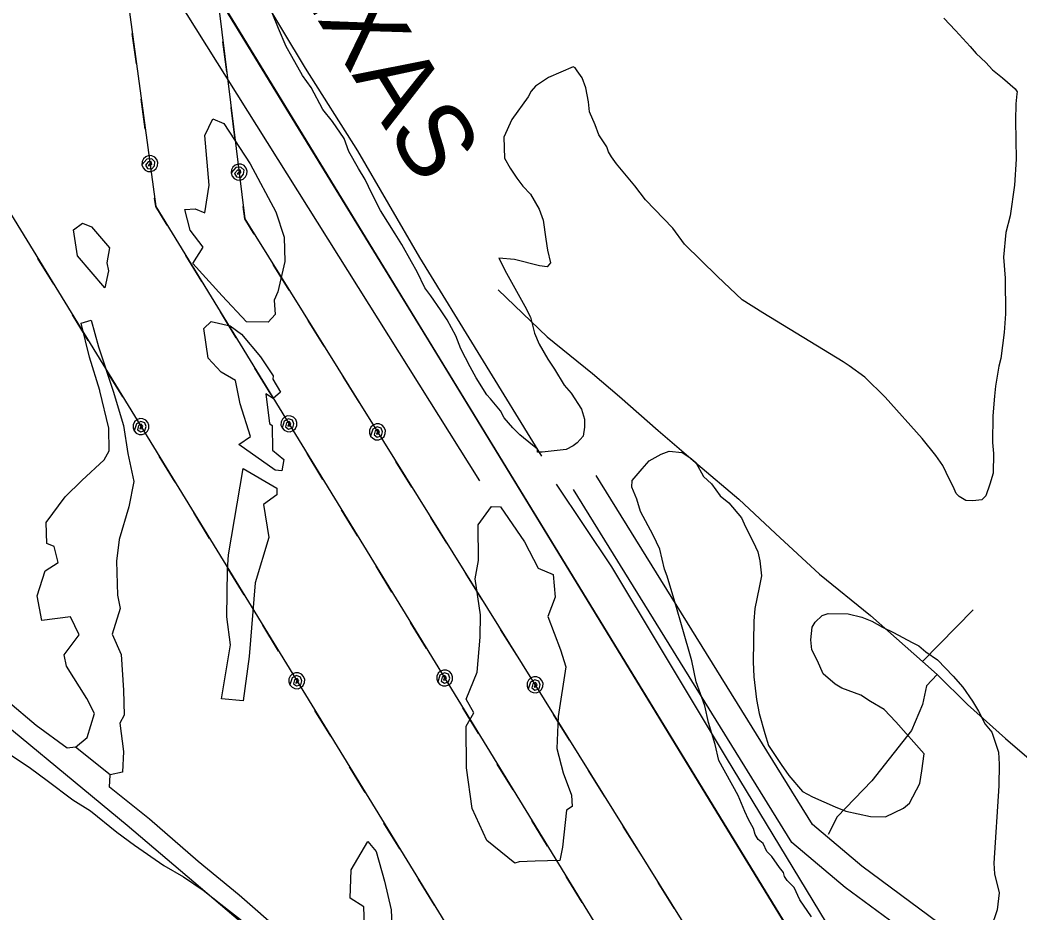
# Model space of a CAD drawing. Extents: x 3263578 to 3301413, y 764927 to 798602.
# Drawn here: x 3268720 to 3269840, y 779917 to 780917 of the extents above; entities that cross this region are included whole.
import ezdxf

# ---------------------------------------------------------------- set-up
doc = ezdxf.new("R2010")
doc.units = 0
for name, color, linetype in [('V-RAIL-IDEN', 7, 'Continuous'), ('V-RAIL-TRAK', 7, 'Continuous'), ('V-ROAD-CNTR', 7, 'Continuous'), ('V-SITE-VEGE', 7, 'Continuous'), ('V-TOPO-SHOR', 7, 'Continuous'), ('V-UTIL-LINE', 7, 'Continuous')]:
    doc.layers.add(name, color=color, linetype=linetype)

msp = doc.modelspace()

# ---------------------------------------------------------------- linework, layer by layer
at = {"layer": 'V-RAIL-TRAK'}
msp.add_lwpolyline([(3270536.8, 778335.8), (3270418.2, 778530.3), (3270314.9, 778698.6), (3270283.6, 778749.8), (3270207, 778874.9), (3270093.6, 779060.7), (3269973.2, 779257.5), (3269816.8, 779512.8), (3269677.5, 779741), (3269504.9, 780022.9), (3269364.8, 780252.1), (3269178.7, 780556.8), (3269021.9, 780812.1), (3268822.8, 781137.8), (3268625.6, 781460.3)], dxfattribs=at)
at = {"layer": 'V-ROAD-CNTR'}
for points in [[(3272188.4, 775832.5), (3271868.1, 776292.7), (3271339.6, 777053.2), (3271160.7, 777323.7), (3270905.4, 777727.5), (3270283.4, 778748.1), (3269657.5, 779774.1), (3268620.7, 781469), (3267728.6, 782934.3)], [(3270148, 779651.3), (3270027.1, 779737), (3269970.2, 779772.8), (3269878.4, 779823.7), (3269781.7, 779881.3), (3269663.2, 779969), (3269607.8, 780015.7), (3269365.5, 780407)], [(3270130.7, 779626.8), (3270010.4, 779712.1), (3269955, 779747), (3269863.4, 779797.7), (3269765.1, 779856.3), (3269644.6, 779945.4), (3269584.8, 779995.8), (3269340, 780391.2)], [(3269089, 779803.1), (3268839.7, 780014.8), (3268651.7, 780170)]]:
    msp.add_lwpolyline(points, dxfattribs=at)
at = {"layer": 'V-SITE-VEGE'}
for p, q in [((3268699.8, 780100.4), (3268731.6, 780078.8)), ((3268731.6, 780078.8), (3268750.3, 780065.2)), ((3268750.3, 780065.2), (3268778.9, 780043.6)), ((3268778.9, 780043.6), (3268798.7, 780031.1)), ((3268798.7, 780031.1), (3268828.3, 780007.3)), ((3268828.3, 780007.3), (3268848, 779992.5)), ((3268848, 779992.5), (3268881, 779969.8)), ((3268881, 779969.8), (3268903, 779957.2)), ((3268903, 779957.2), (3268925, 779942.4)), ((3268925, 779942.4), (3268944.8, 779926.5)), ((3268944.8, 779926.5), (3268975.5, 779902.7))]:
    msp.add_line(p, q, dxfattribs=at)
for points in [[(3269123.9, 780703.7), (3269114.2, 780722.7), (3269106.7, 780738.4), (3269099.1, 780750.7), (3269088.3, 780769.8), (3269083, 780784.3), (3269070, 780803.4), (3269059.1, 780816.9), (3269046.1, 780841.6), (3269036.3, 780855.1), (3269024.5, 780876.4), (3269018, 780887.6), (3269009.4, 780907.7), (3268996.6, 780939)], [(3269755.2, 780919.1), (3269768.3, 780905.5), (3269784.7, 780887.5), (3269791.2, 780879.6), (3269802.2, 780869.4), (3269809.8, 780861.5), (3269820.8, 780852.5), (3269835, 780840), (3269837.2, 780836.7), (3269837.1, 780834.4), (3269835.9, 780823.3), (3269835.6, 780804.5), (3269836, 780761.1), (3269834.4, 780732.3), (3269829.4, 780697.9), (3269824.6, 780679.1), (3269822, 780651.3)], [(3269811.7, 780495.9), (3269810.2, 780473.7), (3269809.8, 780443.8), (3269810.7, 780431.5), (3269810.3, 780409.3), (3269806.8, 780397.1), (3269802.1, 780383.9), (3269797.6, 780379.5), (3269787.6, 780378.5), (3269779.8, 780378.7), (3269772.1, 780383.2), (3269768.8, 780386.6), (3269765.6, 780394.5), (3269761.3, 780402.3), (3269753.8, 780418), (3269746.2, 780429.2), (3269730.9, 780448.3), (3269689.5, 780494.6), (3269666.5, 780517.2), (3269648.9, 780529.7), (3269642.3, 780534.2), (3269552.1, 780589), (3269529, 780603.8), (3269501.6, 780629.8), (3269464.4, 780666), (3269451.4, 780684), (3269420.8, 780715.6), (3269408.8, 780731.3), (3269388.1, 780756.1), (3269382.7, 780764), (3269379.4, 780769.6), (3269377.3, 780775.1), (3269368.6, 780788.6), (3269364.4, 780799.8), (3269357.9, 780814.4), (3269357, 780825.5), (3269353.9, 780841.1), (3269349.6, 780852.3), (3269344.2, 780860.1), (3269342, 780863.5), (3269339.8, 780864.6), (3269311.9, 780852.9), (3269297.3, 780843.1), (3269292.7, 780837.6), (3269289.3, 780831), (3269271.1, 780805.7), (3269261.9, 780785.9), (3269262.6, 780762.5), (3269269.1, 780751.3), (3269276.7, 780740.1), (3269283.2, 780731.1), (3269292, 780722.1), (3269301.7, 780705.2), (3269306, 780693), (3269309, 780671.8), (3269311, 780659.5), (3269314.1, 780645.1), (3269310.7, 780640.7), (3269301.8, 780641.9), (3269274.1, 780649), (3269256.4, 780650.4), (3269265, 780633.6), (3269285.5, 780596.6), (3269292, 780584.3), (3269296.2, 780566.4), (3269301.5, 780554.1), (3269311.2, 780537.3), (3269318.8, 780526.1), (3269329.7, 780508.1), (3269337.3, 780499.1), (3269349.2, 780481.1), (3269352.4, 780470), (3269352.2, 780461.1), (3269351, 780451.1), (3269344.2, 780443.4), (3269339.7, 780440.2), (3269331.8, 780435.9), (3269321.8, 780434.9), (3269305.1, 780433), (3269299.6, 780433.1), (3269299.6, 780436.4), (3269294.1, 780440.9), (3269279.9, 780452.3), (3269272.2, 780460.2), (3269262.4, 780471.4), (3269258.1, 780479.3), (3269247.2, 780492.8), (3269242.8, 780497.3), (3269230.9, 780516.4), (3269224.4, 780528.7), (3269213.6, 780548.9), (3269208.3, 780563.4), (3269198.6, 780581.3), (3269191, 780592.6), (3269180.2, 780608.3), (3269173.6, 780617.3), (3269165, 780635.2), (3269158.5, 780646.4), (3269147.7, 780665.5), (3269140.2, 780677.8), (3269123.9, 780703.7)], [(3269822, 780651.3), (3269823.8, 780628), (3269824.3, 780588), (3269822.9, 780566.9), (3269819.1, 780538), (3269816.7, 780529.2), (3269813, 780507), (3269811.7, 780495.9)], [(3269606.8, 779912.5), (3269593.8, 779931.6), (3269587.3, 779945.1), (3269579.7, 779953), (3269576.4, 779957.5), (3269575.4, 779961.9), (3269571, 779967.6), (3269562.3, 779979.9), (3269556.8, 779985.6), (3269552.5, 779994.5), (3269547.1, 779999.1), (3269543.8, 780004.7), (3269541.7, 780011.4), (3269536.3, 780021.5), (3269532, 780030.4), (3269524.5, 780048.3), (3269502.9, 780087.6), (3269498.8, 780105.4), (3269491.4, 780130), (3269487.2, 780148.9), (3269477.7, 780175.7), (3269472.5, 780199.2), (3269462, 780237.1), (3269454.6, 780261.7), (3269445.1, 780294), (3269441.9, 780301.9), (3269436.7, 780324.2), (3269429.2, 780339.9), (3269415.2, 780366.7), (3269410.9, 780380.2), (3269405.6, 780393.6), (3269405.7, 780401.3), (3269417.1, 780414.5), (3269425, 780423.3), (3269438.4, 780430.8), (3269447.4, 780434), (3269461.8, 780432.7), (3269470.6, 780427), (3269477.2, 780421.3), (3269485.8, 780405.6), (3269494.6, 780397.7), (3269504.3, 780384.2), (3269514.2, 780376.3), (3269528.4, 780359.4), (3269532.7, 780349.3), (3269541.3, 780332.5), (3269546.7, 780321.3), (3269548.7, 780311.3), (3269550.7, 780294.6), (3269548.3, 780281.3), (3269543.4, 780258), (3269542.1, 780243.6), (3269541.4, 780198), (3269542.2, 780181.4), (3269545.1, 780155.8), (3269548.2, 780140.2), (3269554.5, 780117.8), (3269558.7, 780104.4), (3269572.9, 780083.1), (3269581.5, 780070.7), (3269596.8, 780052.7), (3269607.8, 780047), (3269633.2, 780035.5), (3269645.3, 780030.8), (3269673, 780024.8), (3269689.7, 780024.6), (3269709.9, 780034.2), (3269716.6, 780039.7)], [(3269716.6, 780039.7), (3269728.1, 780061.7), (3269730.5, 780076.1), (3269733, 780095), (3269701.4, 780131), (3269688.3, 780144.6), (3269672.9, 780153.7), (3269661.9, 780160.6), (3269640.9, 780168.7), (3269633.2, 780173.2), (3269620, 780184.6), (3269613.6, 780199.1), (3269607.1, 780211.4), (3269606.2, 780222.6), (3269607.5, 780237), (3269611, 780242.5), (3269618.9, 780250.1), (3269625.6, 780252.3), (3269647.8, 780251.9), (3269663.3, 780248.3), (3269674.3, 780243.7), (3269686.4, 780236.8), (3269698.6, 780231.1), (3269719.5, 780219.6), (3269727.2, 780216.2), (3269734.9, 780209.4), (3269748.1, 780200.3), (3269765.6, 780182.2), (3269776.5, 780169.8), (3269787.3, 780154.1), (3269793.8, 780142.9), (3269801.4, 780128.3), (3269809, 780119.3), (3269816.4, 780097), (3269817.3, 780083.6), (3269816.9, 780059.2), (3269811.1, 779972.6)], [(3269811.1, 779972.6), (3269812, 779960.4), (3269817.2, 779939.2), (3269814.7, 779920.3), (3269807.7, 779899.3)]]:
    msp.add_lwpolyline(points, dxfattribs=at)
at = {"layer": 'V-TOPO-SHOR'}
for p, q in [((3268638, 781351.5), (3269234.8, 780400.7)), ((3268809.2, 780502), (3268797.5, 780539.6)), ((3269731.2, 780198.3), (3269788, 780256.3))]:
    msp.add_line(p, q, dxfattribs=at)
for points in [[(3268699, 781416.4), (3268751.7, 781332.9), (3268805, 781246.6), (3268850, 781171.5), (3268897.7, 781094.5), (3268938.6, 781028.8), (3268989.6, 780946.3), (3269039.4, 780863.4), (3269098.1, 780770.7), (3269167.6, 780651), (3269304.1, 780428.6)], [(3268931.8, 780732.1), (3268927, 780787.7), (3268935.9, 780806.3), (3268948.1, 780801.3), (3268977.7, 780755.9), (3269006.6, 780702.1), (3269015.7, 780674), (3269016.7, 780646.8), (3269008.8, 780612.7), (3269004.7, 780603.2), (3269005.7, 780587.3), (3268997.9, 780578.6), (3268973.6, 780579), (3268946.2, 780608.1), (3268913.4, 780644.3), (3268925.1, 780662.6), (3268910.6, 780681.9), (3268904.6, 780704.9), (3268916.2, 780705.6), (3268926.9, 780701.1), (3268931.8, 780732.1)], [(3268779.6, 780682.1), (3268789.7, 780689.4), (3268800, 780685.3), (3268820, 780662.1), (3268817.1, 780645), (3268819, 780636.1), (3268814.9, 780617), (3268784, 780653.1), (3268779.6, 780682.1)], [(3269255.8, 780614.8), (3269310.4, 780562.4), (3269361.3, 780521.2), (3269391.6, 780495.2), (3269435.1, 780457.2), (3269479.4, 780419.2), (3269525.5, 780380.2), (3269566.4, 780341.9), (3269615.8, 780296.2), (3269672.9, 780250.1), (3269731.2, 780198.3), (3269747.7, 780184), (3269781.6, 780150.4), (3269824.3, 780112.3), (3269869.1, 780073.8), (3269915.6, 780033.5), (3269921.7, 780027.8)], [(3268797.5, 780539.6), (3268788.3, 780577.5), (3268799.5, 780580.8), (3268807.8, 780551), (3268824, 780501.5), (3268835.8, 780462.7), (3268840.4, 780431.6), (3268847.2, 780400), (3268841.7, 780371.6), (3268830.9, 780335.1), (3268827.9, 780310.7), (3268829.1, 780272.8), (3268832.1, 780258), (3268823, 780229.2), (3268833.1, 780206.2), (3268835.8, 780166.3), (3268836.4, 780138.2), (3268831.5, 780129.4), (3268835.9, 780097.5), (3268834.6, 780074.3), (3268820.8, 780071.6), (3268782, 780102.5), (3268795, 780113.4), (3268803.1, 780140.2), (3268794.6, 780157.1), (3268771.8, 780193.4), (3268769.3, 780206), (3268786.1, 780228.4), (3268776.3, 780248.5), (3268744.2, 780244.4), (3268739, 780272), (3268748, 780299.9), (3268762.5, 780309.5), (3268758, 780327.2), (3268749.8, 780330.5), (3268749.1, 780354.3), (3268770.2, 780382.9), (3268788.9, 780401.2), (3268814, 780424.5), (3268819.7, 780434.6), (3268819.2, 780459.8), (3268809.3, 780501.8), (3268809.2, 780502)], [(3268961.4, 780513.2), (3268945.2, 780522.7), (3268930.5, 780538.2), (3268925.6, 780571.6), (3268934.1, 780579.5), (3268955.1, 780574.6), (3268967.9, 780565.2), (3268989.2, 780539.8), (3269003.5, 780518.7), (3269003.1, 780514.8), (3269011.6, 780500.1), (3269003.6, 780493), (3268995.3, 780498.2), (3268999.3, 780465.2), (3269002.5, 780462.7), (3269002.8, 780435.1), (3269015.3, 780424.8), (3269013.3, 780412.1), (3269005.8, 780413), (3268965.1, 780441.7), (3268978.1, 780450.7), (3268966.3, 780487), (3268961.4, 780513.2)], [(3268782, 780102.5), (3268772.6, 780101.2), (3268737.7, 780126.9), (3268673.9, 780180.5), (3268611.9, 780235), (3268549, 780287.4), (3268489, 780337.3), (3268427, 780390.9), (3268370.2, 780435)], [(3268976.7, 780204.2), (3268970, 780154.4), (3268945.4, 780156.6), (3268955.8, 780217.1), (3268951.5, 780248.6), (3268952.3, 780301), (3268953.4, 780317.9), (3268969.9, 780414.6), (3269007.7, 780392.7), (3269007.5, 780385.1), (3268992.8, 780374.4), (3268998.5, 780337.4), (3268983.2, 780286.5), (3268976.7, 780204.2)], [(3269320.5, 780397.2), (3269382.8, 780304.5), (3269437.1, 780213.7), (3269511.3, 780090.4), (3269623.2, 779905.7), (3269693.9, 779782.8)], [(3269248, 780372.1), (3269258.3, 780371.9), (3269285.2, 780332.4), (3269300.5, 780303), (3269317.2, 780295.9), (3269319.6, 780270.4), (3269311.2, 780248.9), (3269325.4, 780211.7), (3269331.6, 780192.6), (3269322.8, 780136.8), (3269321.3, 780100.9), (3269328.5, 780073.7), (3269337.8, 780048.8), (3269338.6, 780036.1), (3269332.2, 780032), (3269327.8, 779990.6), (3269324.9, 779975.5), (3269297.2, 779974.7), (3269279.3, 779974.1), (3269274.2, 779972.4), (3269242.8, 779998), (3269226.4, 780033.7), (3269220.3, 780079.5), (3269219.7, 780126.1), (3269228.5, 780140.9), (3269219.8, 780156.2), (3269232.2, 780186.4), (3269235.4, 780225.7), (3269235.8, 780250.6), (3269230, 780291), (3269233.4, 780311.7), (3269233.2, 780351.7), (3269248, 780372.1)], [(3269747.7, 780184), (3269735.5, 780171.2), (3269731.2, 780150.1), (3269718.9, 780121.2), (3269674.5, 780064.7), (3269635.7, 780024.6), (3269625.6, 780004.8)], [(3269013.6, 779894.6), (3268965.5, 779936.5), (3268919.3, 779974.4), (3268864.8, 780021.7), (3268820.1, 780057.7), (3268820.8, 780071.6)], [(3269109.6, 779996.8), (3269119, 779985.6), (3269128.3, 779952.3), (3269135.8, 779920.2), (3269137.1, 779886.5), (3269106.7, 779881.4), (3269105, 779923.7), (3269089.6, 779933.4), (3269091, 779965.1), (3269109.6, 779996.8)]]:
    msp.add_lwpolyline(points, dxfattribs=at)
at = {"layer": 'V-UTIL-LINE'}
for points in [[(3268409.4, 784958.9), (3268573.9, 783710.2), (3268827.4, 781865), (3268971.7, 780694.4), (3269579.3, 779719.4), (3271430.8, 776750.8), (3272074.8, 775829.8)], [(3268230.1, 784805.8), (3268307.9, 784237.2), (3268452.8, 783310.2), (3268587.3, 782316.5), (3268362.2, 781702.1), (3268263.1, 781437.2), (3268500, 781041.3), (3269699.7, 779084.3), (3270893.5, 777127.6), (3271403.4, 776393.4), (3271797.6, 775829.7)], [(3268411.5, 784147.1), (3268571.4, 782890.1), (3268740.1, 781681.1), (3268871.8, 780708.4), (3269952.3, 778945), (3271642.6, 776301.9), (3271967.2, 775831.8)], [(3268850.2, 780868.2), (3268845.6, 780901.9)], [(3268951.4, 780859), (3268947.2, 780892.8)], [(3268860.1, 780794.9), (3268855.5, 780828.6)], [(3268960.5, 780785.6), (3268956.3, 780819.3)], [(3268865.3, 780756.2), (3268863.2, 780754.3), (3268865.5, 780753.8), (3268867.5, 780755.7), (3268866.7, 780758.5), (3268863.4, 780758.2), (3268860.4, 780754.6), (3268862.7, 780751), (3268867.5, 780750.3), (3268870.5, 780753.8), (3268870.9, 780758.3), (3268867.3, 780761.6), (3268861.8, 780761.1), (3268856.4, 780755), (3268857.6, 780751.7), (3268859.9, 780749.1), (3268863, 780747.5), (3268866.5, 780747.3), (3268869.9, 780748.5), (3268872.5, 780750.8), (3268874, 780753.9), (3268874.2, 780757.5), (3268873.1, 780760.8), (3268870.8, 780763.4), (3268867.6, 780764.9), (3268864.1, 780765.2), (3268860.8, 780764), (3268858.2, 780761.7), (3268856.6, 780758.5), (3268856.4, 780755)], [(3268965.2, 780746.9), (3268963.1, 780745), (3268965.3, 780744.4), (3268967.3, 780746.3), (3268966.7, 780749.1), (3268963.3, 780748.9), (3268960.3, 780745.3), (3268962.5, 780741.6), (3268967.4, 780740.9), (3268970.3, 780744.4), (3268970.8, 780748.8), (3268967.3, 780752.2), (3268961.8, 780751.8), (3268956.3, 780745.8), (3268957.4, 780742.4), (3268959.7, 780739.8), (3268962.8, 780738.2), (3268966.3, 780737.9), (3268969.7, 780739), (3268972.3, 780741.3), (3268973.9, 780744.5), (3268974.2, 780748), (3268973.1, 780751.3), (3268970.8, 780754), (3268967.6, 780755.5), (3268964.1, 780755.8), (3268960.8, 780754.7), (3268958.1, 780752.4), (3268956.6, 780749.3), (3268956.3, 780745.8)], [(3268884.7, 780687.3), (3268871.8, 780708.4), (3268870.6, 780717.6)], [(3268982.3, 780677.3), (3268971.7, 780694.4), (3268970, 780708.2)], [(3268923.4, 780624.2), (3268905.6, 780653.2)], [(3268757.6, 780621.1), (3268739.8, 780650.1)], [(3269021.5, 780614.5), (3269003.5, 780643.4)], [(3268796.3, 780558), (3268778.5, 780587)], [(3268962, 780561.1), (3268944.3, 780590.1)], [(3269060.6, 780551.7), (3269042.6, 780580.6)], [(3268835, 780494.9), (3268817.2, 780523.9)], [(3269000.7, 780498), (3268982.9, 780527)], [(3269099.7, 780488.9), (3269081.8, 780517.8)], [(3269021.1, 780464.8), (3269019.9, 780462.1), (3269022.2, 780462.6), (3269023.2, 780465.1), (3269021.4, 780467.4), (3269018.5, 780465.8), (3269017.3, 780461.3), (3269020.8, 780458.9), (3269025.5, 780460.2), (3269026.8, 780464.6), (3269025.3, 780468.9), (3269020.8, 780470.4), (3269015.9, 780467.8), (3269013.4, 780460.1), (3269015.8, 780457.5), (3269019, 780456), (3269022.5, 780455.9), (3269025.8, 780457.1), (3269028.4, 780459.5), (3269029.8, 780462.7), (3269030, 780466.2), (3269028.8, 780469.5), (3269026.4, 780472.1), (3269023.2, 780473.5), (3269019.7, 780473.7), (3269016.4, 780472.5), (3269013.8, 780470.1), (3269012.3, 780466.9), (3269012.2, 780463.4), (3269013.4, 780460.1)], [(3268855.3, 780461.7), (3268854.2, 780459.1), (3268856.5, 780459.5), (3268857.5, 780462), (3268855.7, 780464.4), (3268852.7, 780462.7), (3268851.5, 780458.2), (3268855.1, 780455.8), (3268859.7, 780457.2), (3268861, 780461.6), (3268859.6, 780465.8), (3268855, 780467.3), (3268850.2, 780464.7), (3268847.7, 780457), (3268850, 780454.4), (3268853.2, 780452.9), (3268856.7, 780452.8), (3268860, 780454), (3268862.6, 780456.4), (3268864.1, 780459.6), (3268864.2, 780463.1), (3268863, 780466.4), (3268860.6, 780469), (3268857.4, 780470.4), (3268853.9, 780470.6), (3268850.6, 780469.4), (3268848.1, 780467), (3268846.6, 780463.8), (3268846.4, 780460.3), (3268847.7, 780457)], [(3269120.4, 780455.8), (3269119.2, 780453.2), (3269121.5, 780453.6), (3269122.5, 780456.2), (3269120.7, 780458.5), (3269117.8, 780456.8), (3269116.6, 780452.3), (3269120.2, 780449.9), (3269124.8, 780451.3), (3269126.1, 780455.7), (3269124.6, 780459.9), (3269120, 780461.5), (3269115.2, 780458.8), (3269112.7, 780451), (3269115.1, 780448.5), (3269118.3, 780447), (3269121.9, 780446.9), (3269125.1, 780448.2), (3269127.7, 780450.6), (3269129.1, 780453.8), (3269129.3, 780457.3), (3269128, 780460.6), (3269125.6, 780463.1), (3269122.4, 780464.6), (3269118.9, 780464.7), (3269115.6, 780463.4), (3269113.1, 780461), (3269111.6, 780457.8), (3269111.5, 780454.3), (3269112.7, 780451)], [(3268893.5, 780399.4), (3268875.7, 780428.4)], [(3269059.2, 780402.5), (3269041.5, 780431.5)], [(3269159, 780393.9), (3269141, 780422.7)], [(3268932.2, 780336.3), (3268914.4, 780365.3)], [(3269097.9, 780339.4), (3269080.1, 780368.4)], [(3269198.1, 780331.1), (3269180.1, 780359.9)], [(3269136.5, 780276.3), (3269118.8, 780305.3)], [(3268970.8, 780273.3), (3268953.1, 780302.2)], [(3269237.3, 780268.2), (3269219.3, 780297.1)], [(3269009.5, 780210.2), (3268991.8, 780239.2)], [(3269175.2, 780213.2), (3269157.4, 780242.2)], [(3269276.4, 780205.4), (3269258.4, 780234.3)], [(3269029.9, 780176.9), (3269028.7, 780174.3), (3269031, 780174.8), (3269032.1, 780177.3), (3269030.3, 780179.6), (3269027.3, 780178), (3269026.1, 780173.4), (3269029.6, 780171.1), (3269034.3, 780172.4), (3269035.6, 780176.8), (3269034.1, 780181), (3269029.6, 780182.6), (3269024.7, 780180), (3269022.2, 780172.2), (3269024.6, 780169.7), (3269027.8, 780168.2), (3269031.3, 780168), (3269034.6, 780169.3), (3269037.2, 780171.6), (3269038.7, 780174.8), (3269038.8, 780178.3), (3269037.6, 780181.6), (3269035.2, 780184.2), (3269032, 780185.7), (3269028.5, 780185.8), (3269025.2, 780184.6), (3269022.6, 780182.2), (3269021.1, 780179), (3269021, 780175.5), (3269022.2, 780172.2)], [(3269195.6, 780180), (3269194.4, 780177.4), (3269196.7, 780177.8), (3269197.7, 780180.3), (3269195.9, 780182.7), (3269193, 780181), (3269191.8, 780176.5), (3269195.3, 780174.1), (3269200, 780175.5), (3269201.3, 780179.9), (3269199.8, 780184.1), (3269195.3, 780185.6), (3269190.4, 780183.1), (3269187.9, 780175.3), (3269190.3, 780172.7), (3269193.5, 780171.2), (3269197, 780171.1), (3269200.3, 780172.3), (3269202.9, 780174.7), (3269204.3, 780177.9), (3269204.5, 780181.4), (3269203.2, 780184.7), (3269200.9, 780187.3), (3269197.7, 780188.7), (3269194.2, 780188.9), (3269190.9, 780187.7), (3269188.3, 780185.3), (3269186.8, 780182.1), (3269186.7, 780178.6), (3269187.9, 780175.3)], [(3269297, 780172.3), (3269295.9, 780169.7), (3269298.2, 780170.2), (3269299.2, 780172.7), (3269297.4, 780175), (3269294.4, 780173.4), (3269293.2, 780168.8), (3269296.8, 780166.5), (3269301.5, 780167.8), (3269302.7, 780172.2), (3269301.2, 780176.5), (3269296.7, 780178), (3269291.8, 780175.4), (3269289.4, 780167.6), (3269291.8, 780165), (3269295, 780163.6), (3269298.5, 780163.5), (3269301.8, 780164.7), (3269304.3, 780167.1), (3269305.8, 780170.3), (3269305.9, 780173.8), (3269304.7, 780177.1), (3269302.3, 780179.7), (3269299.1, 780181.1), (3269295.6, 780181.2), (3269292.3, 780180), (3269289.7, 780177.6), (3269288.3, 780174.4), (3269288.1, 780170.9), (3269289.4, 780167.6)], [(3269233.7, 780117.7), (3269216, 780146.7)], [(3269068.1, 780114.7), (3269050.3, 780143.7)], [(3269335.6, 780110.4), (3269317.6, 780139.2)], [(3269106.7, 780051.6), (3269089, 780080.6)], [(3269272.4, 780054.6), (3269254.6, 780083.6)], [(3269374.8, 780047.6), (3269356.8, 780076.4)], [(3269145.4, 779988.5), (3269127.6, 780017.5)], [(3269311, 779991.5), (3269293.3, 780020.5)], [(3269413.9, 779984.8), (3269395.9, 780013.6)], [(3269349.7, 779928.4), (3269331.9, 779957.4)], [(3269184.1, 779925.4), (3269166.3, 779954.4)], [(3269453, 779922), (3269435.1, 779950.8)]]:
    msp.add_lwpolyline(points, dxfattribs=at)

# ---------------------------------------------------------------- texts
at = {"layer": 'V-RAIL-IDEN'}
msp.add_text('TEXAS', height=83, rotation=301.8015, dxfattribs=at).set_placement((3268977.4, 781039.1))

doc.saveas('drawing.dxf')
